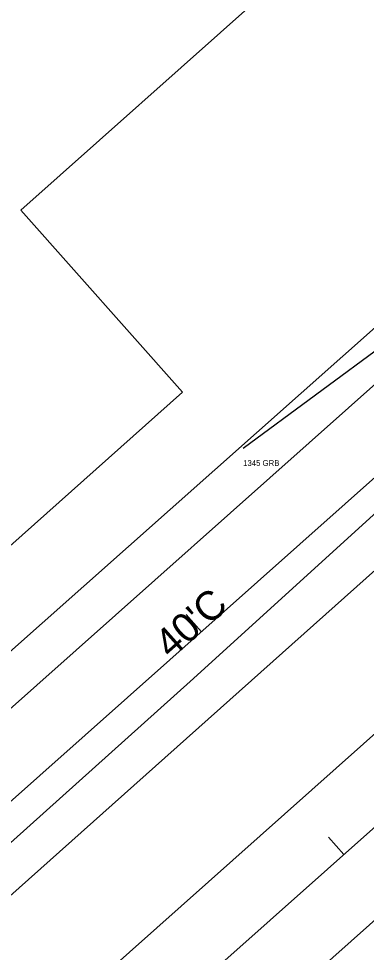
# Model space of a CAD drawing. Extents: x 50001 to 56005, y 49075 to 53926.
# Drawn here: x 53335.6 to 53395.5, y 51359 to 51519.9 of the extents above; entities that cross this region are included whole.
import ezdxf

# ---------------------------------------------------------------- set-up
doc = ezdxf.new("R2010")
doc.units = 0
for name, color, linetype in [('Level 1', 7, 'Continuous'), ('Level 11', 7, 'Continuous'), ('Level 12', 7, 'Continuous'), ('Level 18', 7, 'Continuous'), ('Level 19', 7, 'Continuous'), ('Level 20', 7, 'Continuous'), ('Level 3', 7, 'Continuous'), ('Level 57', 7, 'Continuous'), ('Level 7', 7, 'Continuous')]:
    doc.layers.add(name, color=color, linetype=linetype)

msp = doc.modelspace()

# ---------------------------------------------------------------- linework, layer by layer
at = {"layer": 'Level 1'}
for p, q in [((52544.81, 50683.3), (55534.58, 53340.86)), ((52714.15, 50773.62), (54181.77, 52078.16)), ((53367.09, 51414.21), (53364.43, 51417.2))]:
    msp.add_line(p, q, dxfattribs=at)
at = {"layer": 'Level 11'}
msp.add_line((53157.7, 51254.45), (53424.49, 51490.93), dxfattribs=at)
at = {"layer": 'Level 12'}
for p, q in [((53573.51, 51698.05), (53335.95, 51486.88)), ((53335.95, 51486.88), (53363.85, 51455.49)), ((52637.37, 50809.73), (53363.85, 51455.49)), ((53407.7, 51406.16), (52566.74, 50658.64))]:
    msp.add_line(p, q, dxfattribs=at)
at = {"layer": 'Level 18'}
for p, q in [((53365.15, 51405.63), (53402.16, 51439.25)), ((53327.91, 51372.27), (53365.15, 51405.63))]:
    msp.add_line(p, q, dxfattribs=at)
at = {"layer": 'Level 19'}
for p, q in [((52714.15, 50773.62), (54181.77, 52078.16)), ((53391.64, 51375.83), (53388.98, 51378.82))]:
    msp.add_line(p, q, dxfattribs=at)
at = {"layer": 'Level 20'}
for p, q in [((52706.17, 50782.58), (53452.43, 51445.92)), ((52722.12, 50764.65), (53468.37, 51427.98))]:
    msp.add_line(p, q, dxfattribs=at)
at = {"layer": 'Level 3'}
for p, q in [((53162.5, 51248.32), (53434.09, 51489.84)), ((53179.35, 51230.72), (53449.72, 51471.81))]:
    msp.add_line(p, q, dxfattribs=at)
at = {"layer": 'Level 7'}
msp.add_line((53399.95, 51464.72), (53374.29, 51445.78), dxfattribs=at)

# ---------------------------------------------------------------- texts
at = {"layer": 'Level 18'}
msp.add_text("40'C", height=5, rotation=41.6333, dxfattribs=at).set_placement((53361.83, 51409.37))
at = {"layer": 'Level 57'}
msp.add_text('1345 GRB', height=1, dxfattribs=at).set_placement((53374.29, 51442.78))

doc.saveas('drawing.dxf')
